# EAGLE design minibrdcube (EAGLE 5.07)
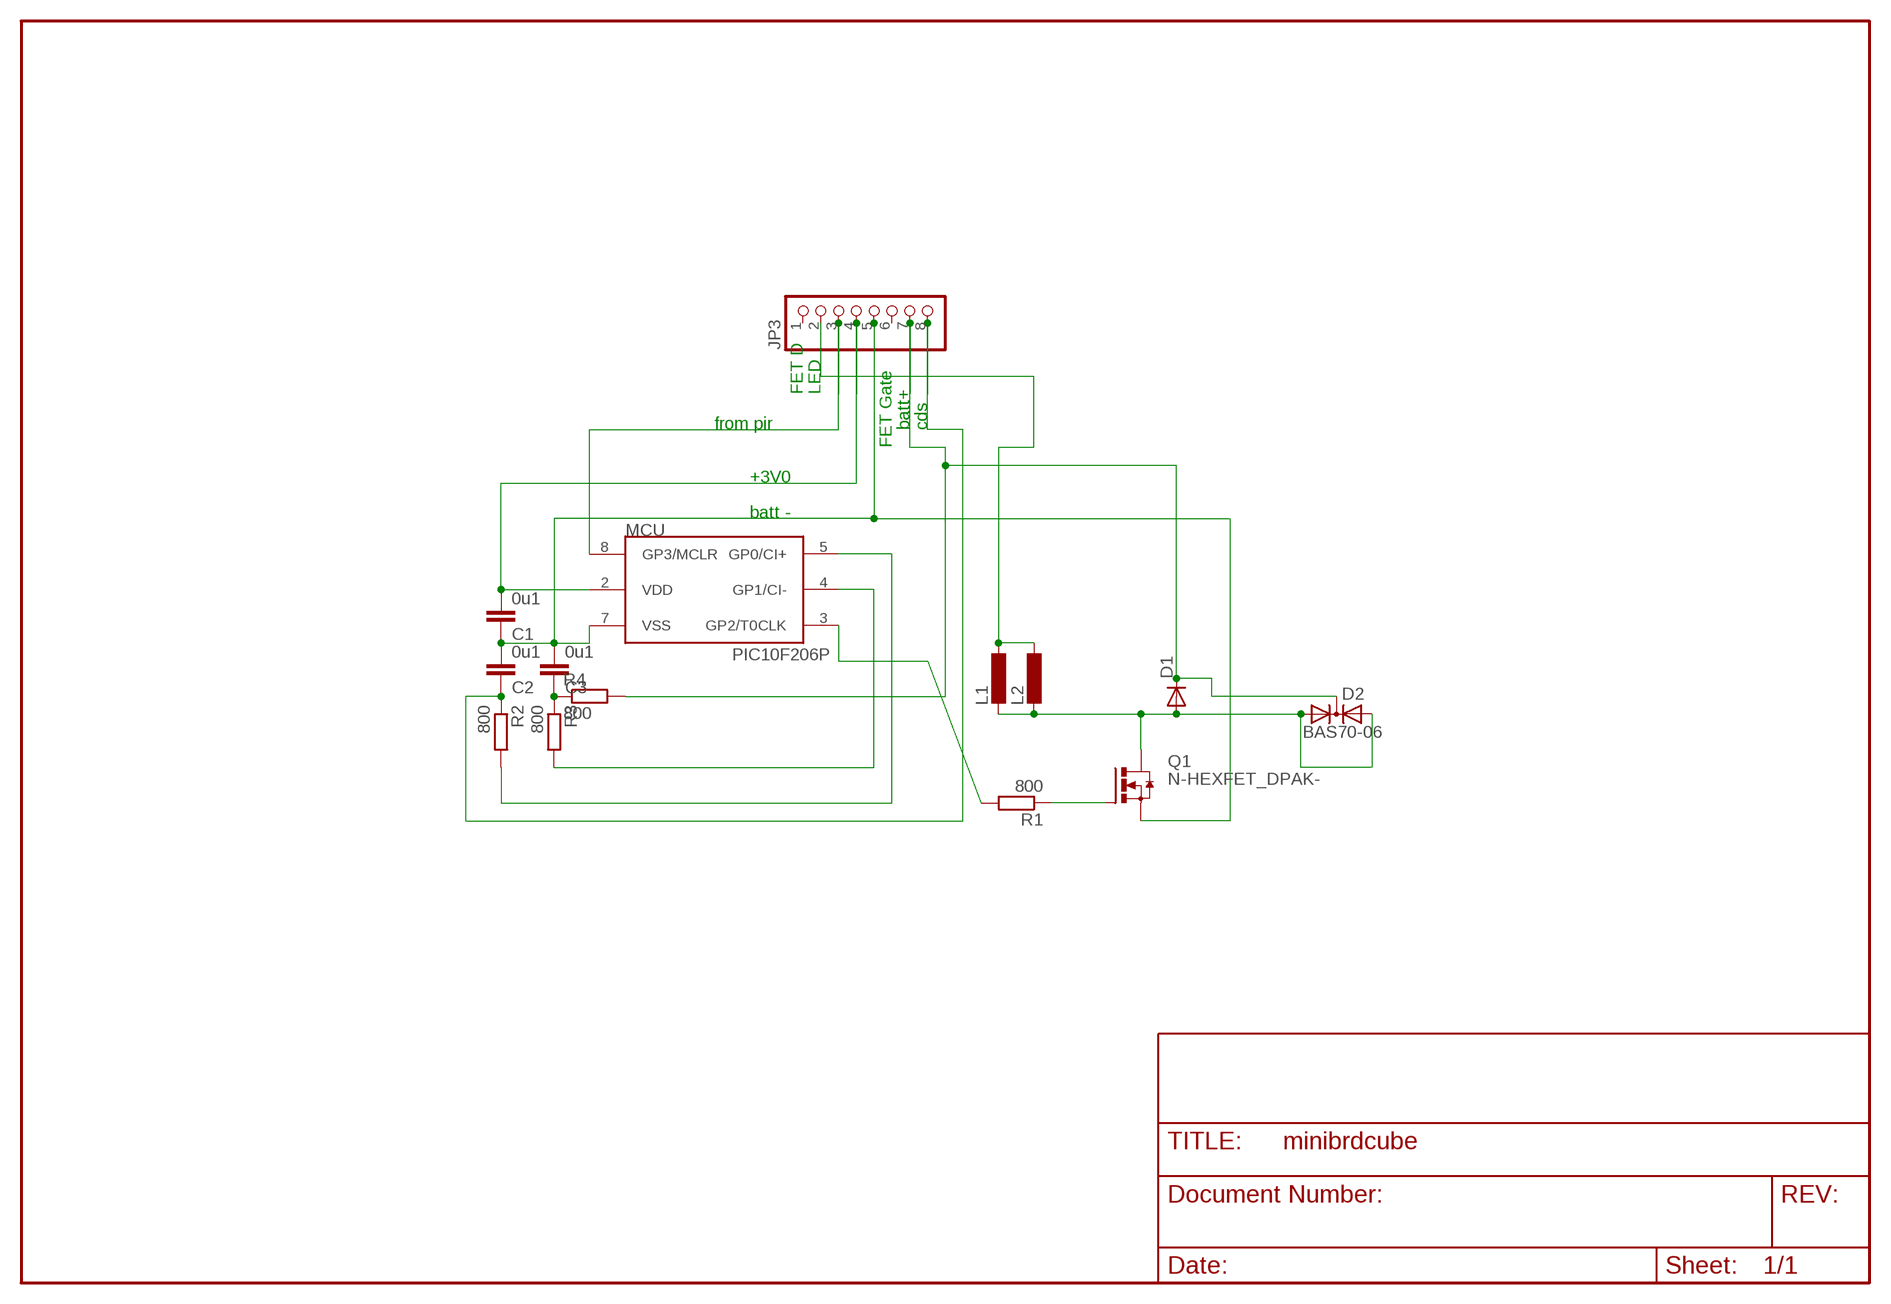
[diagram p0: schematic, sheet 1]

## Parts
C1  0u1  C-EUC1206  [C1206]
C2  0u1  C-EUC1206  [C1206]
C3  0u1  C-EUC1206  [C1206]
D1  DIODE-SMC  [SMC]
D2  BAS70-06  [SOT23]
JP3  PINHD-1X8  [1X08]
L1  L-EUOPEN  [OPEN5]
L2  L-EUPIS2816  [PIS2816]
MCU  PIC10F206P  [DIL8]
Q1  N-HEXFET_DPAK-  [TO252]
R1  800  R-EU_R1206  [R1206]
R2  800  R-EU_R1206  [R1206]
R3  800  R-EU_R1206  [R1206]
R4  800  R-EU_R1206  [R1206]

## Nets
N$1: C1.1 C2.2 C3.2 JP3.5 MCU.7(VSS) Q1.2(S)
N$2: MCU.5(GP0/CI+) R2.2
N$3: D1.C D2.3(C) JP3.7 R4.2
N$4: MCU.4(GP1/CI-) R3.2
N$5: D1.A D2.1(A1) D2.2(A2) L1.2 L2.2 Q1.3(D)
N$6: C1.2 JP3.4 MCU.2(VDD)
N$7: Q1.1(G) R1.1
N$8: JP3.2 L1.1 L2.1
N$10: C3.1 R3.1 R4.1
N$11: C2.1 JP3.8 R2.1
N$13: JP3.3 MCU.8(GP3/MCLR)
N$14: MCU.3(GP2/T0CLK) R1.2
Unconnected: JP3.1 JP3.6

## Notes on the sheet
- FET D | LED
- from pir | batt+ | cds
- FET Gate
- +3V0
- batt -

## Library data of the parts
C1-C3 = rcl:C-EU: CAPACITOR, European symbol
D1 = diode-1:DIODE-: DIODE
D2 = diode-1:BAS70-06: Silicon Schottky Diodes General-purpose diode for high-speed switching
JP3 = pinhead(2):PINHD-1X8: PIN HEADER
L1 L2 = rcl:L-EU: INDUCTOR, European symbol
MCU = microchip-3:PIC10F2*: uPC nW 0,25/0,5k Program Flash memory Comparator
Q1 = transistor-power:N-HEXFET_?-*: HEXFET® Power MOSFET
R1-R4 = rcl:R-EU_: RESISTOR, European symbol

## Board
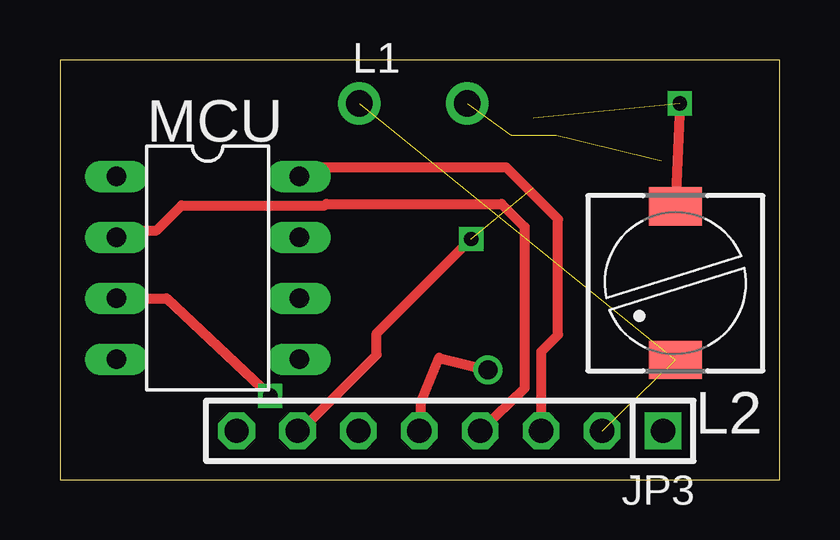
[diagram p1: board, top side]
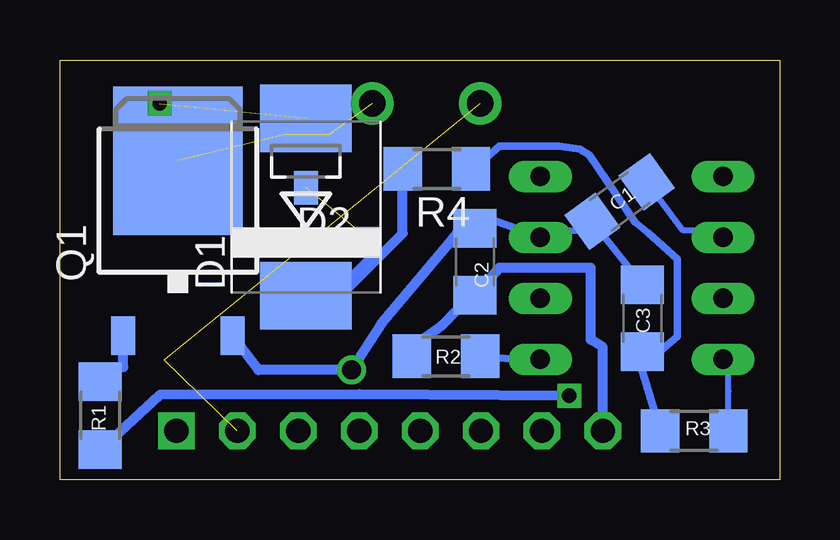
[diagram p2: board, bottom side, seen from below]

Size 30 x 17.5 mm. Coordinates in mm from the lower left corner, seen from the top.
Outline: 0,0 30,0 30,17.5 0,17.5 0,0
Copper layers (1*16): Top 0.035mm / dielectric 1.5mm / Bottom 0.035mm
Design rules "default": minimum track width 10mil, minimum drill 24mil, track to track 8mil, track to pad 8mil, pad to pad 8mil, via to via 8mil, smd to smd 8mil, copper to edge 1mil, drill to drill 8mil, minimum pad ring 10mil, minimum via ring 8mil, stop-mask expansion 4mil, vias tented up to drill 0mil, thermal gap 10mil

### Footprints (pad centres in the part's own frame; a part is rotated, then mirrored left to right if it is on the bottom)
C1206 = smd 1.6 x 1.8: 1 -1.4,0; 2 1.4,0
SMC = smd 2.8 x 3.8: A 3.7,0; C -3.7,0
SOT23 = smd 1 x 1.4: 1 -0.95,-1.1; 2 0.95,-1.1; 3 0,1.1
1X08 = drill 1.016 square: 1 -8.89,0 | drill 1.016 octagon: 2 -6.35,0; 3 -3.81,0; 4 -1.27,0; 5 1.27,0; 6 3.81,0; 7 6.35,0; 8 8.89,0
OPEN5 = drill 1.1 pad 1.778 round: 1 -2.25,0; 2 2.25,0
PIS2816 = smd 2.2 x 1.6: 1 0,3.2; 2 0,-3.2
DIL8 = drill 0.813 long: 1 -3.81,-3.81; 2 -1.27,-3.81; 3 1.27,-3.81; 4 3.81,-3.81; 5 3.81,3.81; 6 1.27,3.81; 7 -1.27,3.81; 8 -3.81,3.81
TO252 = smd 1 x 1.6: 1 -2.28,-3.53; 2 2.28,-3.53 | smd 5.4 x 6.2: 3 0,3.77
R1206 = smd 1.6 x 1.803: 1 -1.422,0; 2 1.422,0

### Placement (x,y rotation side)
C1  6.67,11.59 35.9 bottom
C2  12.7,9.08 90 bottom
C3  5.71,6.73 90 bottom
D1  19.75,11.37 90 bottom
D2  19.75,13.27 180 bottom
JP3  16.26,2.03 180 top
L1  14.73,15.68 0 top
L2  25.65,8.19 180 top
MCU  6.16,8.83 270 top
Q1  25.08,9.53 0 bottom
R1  28.32,2.67 270 bottom
R2  13.91,5.14 0 bottom
R3  3.56,2.03 0 bottom
R4  14.29,12.95 180 bottom

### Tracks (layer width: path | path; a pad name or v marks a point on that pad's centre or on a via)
N$1  (via drill 0.8)
  Top 0.406: v17.84,4.57 15.81,5.08 15.05,3.24 15.05,2.1 JP3.5
  Bottom 0.254: C1.1 8.32,10.39 8.73,10.39 MCU.7
  Bottom 0.305: C2.2 12.07,10.86 10.1,10.16 MCU.7 | C1.1 7.75,10.67 C3.2
  Bottom 0.406: Q1.2 21.72,4.57 v17.84,4.57 16.57,6.54 13.78,9.84 13.27,10.48 C2.2
N$2
  Bottom 0.305: MCU.5 10.1,4.95 R2.2
N$3  (via drill 0.6)  (1 unrouted)
  Top 0.406: JP3.7 10.03,2.03 13.21,5.21 13.21,6.1 v17.14,10.03
  Bottom 0.305: 15.71,12.91 R4.2
  Bottom 0.406: 15.71,12.91 15.71,10.26 17.91,8.06 18.22,8.06 | 18.22,8.06 19.35,8.06 D1.C | v17.14,10.03 17.14,9.14 18.22,8.06
N$4
  Bottom 0.254: R3.2 2.13,3.69 2.13,4.39 MCU.4
N$5  (via drill 0.6)  (4 unrouted)
  Top 0.406: v25.84,15.68 L2.2
  Bottom 0.406: Q1.3 v25.84,15.68
N$6
  Top 0.406: JP3.4 19.37,3.81 19.37,10.54 18.41,11.49 11.11,11.49 11.05,11.43 5.07,11.43 4.03,10.39 2.64,10.39 MCU.2
  Bottom 0.254: C1.2 4.03,10.39 3.63,10.39 MCU.2
N$7
  Bottom 0.406: Q1.1 27.36,4.69 27.75,4.57 27.98,4.19 R1.1
N$8  (2 unrouted)
N$10
  Bottom 0.305: R4.1 12.76,12.95 11.68,13.91 9.21,13.91 8.32,13.78 7.94,13.53 6.03,10.73 5.46,10.29 4.25,9.21 4.25,5.97 5.02,5.33 C3.1 5.97,5.33 R3.1
N$11
  Bottom 0.406: R2.1 15.3,5.55 14.1,6.41 13.46,7.04 C2.1 11.68,8.83 7.87,8.83 7.87,5.84 7.37,5.52 JP3.8
N$13
  Top 0.406: JP3.3 20.07,5.33 20.77,6.03 20.77,10.86 18.61,13.02 10.35,13.02 MCU.8
N$14  (via drill 0.6)
  Top 0.406: MCU.3 4.45,7.56 v8.76,3.49
  Bottom 0.406: v8.76,3.49 17.53,3.56 25.84,3.53 R1.2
